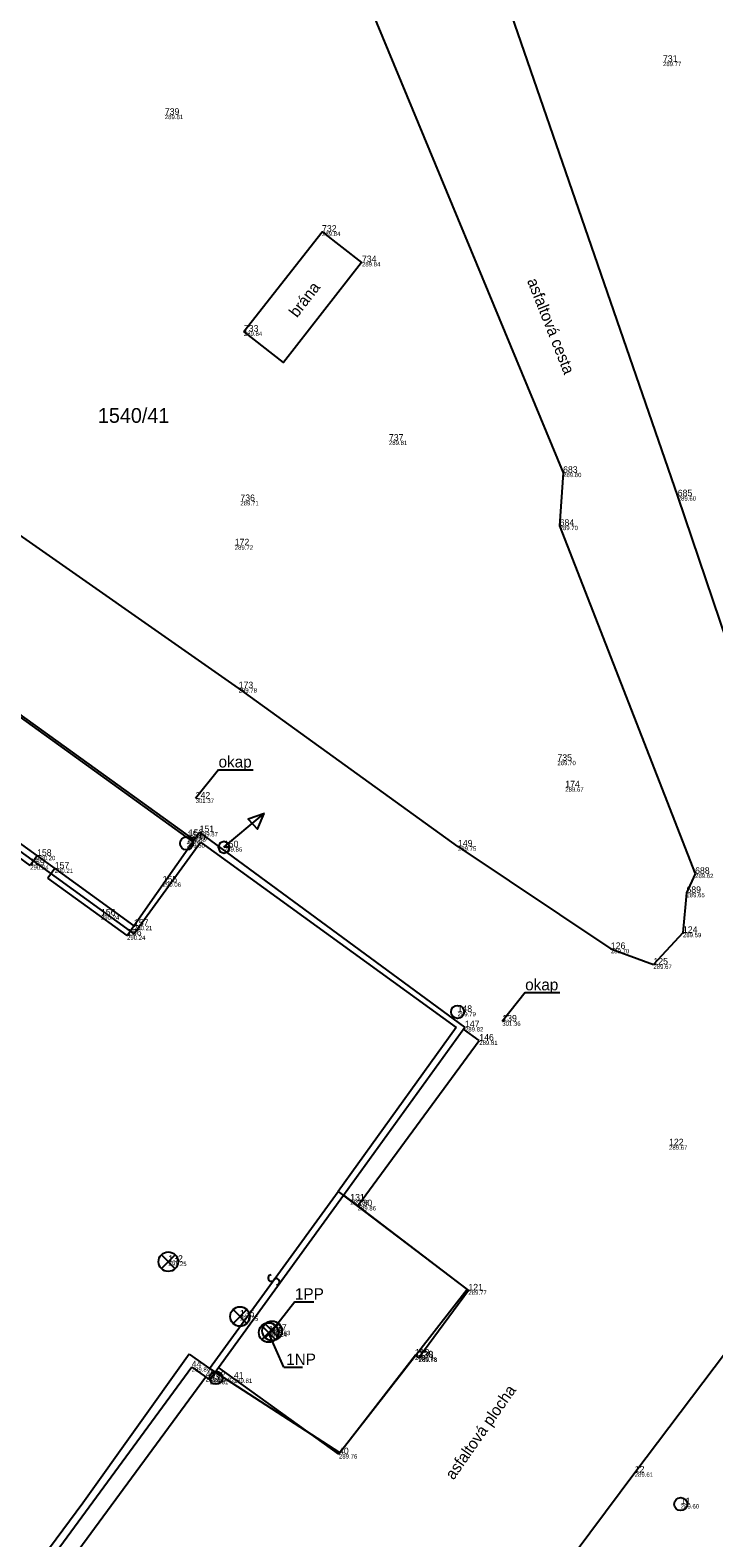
# Model space of a CAD drawing. Extents: x -805057 to -804930, y -994399 to -994240.
# Drawn here: x -804995.35 to -804979.61, y -994342.6 to -994307.89 of the extents above; entities that cross this region are included whole.
import ezdxf

# ---------------------------------------------------------------- set-up
doc = ezdxf.new("R2010")
doc.units = 0
for name, color, linetype in [('bod cislo', 7, 'Continuous'), ('bod pozice', 7, 'Continuous'), ('bod výška', 7, 'Continuous'), ('branka', 7, 'Continuous'), ('budova', 7, 'Continuous'), ('kanalizace', 7, 'Continuous'), ('Katastralni mapa', 7, 'Continuous'), ('komunikace', 7, 'Continuous'), ('podlaha', 7, 'Continuous'), ('popis', 7, 'Continuous'), ('svod', 7, 'Continuous'), ('zemnění', 7, 'Continuous')]:
    doc.layers.add(name, color=color, linetype=linetype)

msp = doc.modelspace()

# ---------------------------------------------------------------- linework, layer by layer
at = {"layer": 'bod pozice'}
for p, q in [((-804980.78, -994308.62), (-804980.78, -994308.62)), ((-804992.25, -994309.84), (-804992.25, -994309.84)), ((-804988.63, -994312.53), (-804988.63, -994312.53)), ((-804987.71, -994313.23), (-804987.71, -994313.23)), ((-804990.43, -994314.83), (-804990.43, -994314.83)), ((-804987.09, -994317.34), (-804987.09, -994317.34)), ((-804983.08, -994318.08), (-804983.08, -994318.08)), ((-804990.51, -994318.73), (-804990.51, -994318.73)), ((-804980.44, -994318.62), (-804980.44, -994318.62)), ((-804983.16, -994319.3), (-804983.16, -994319.3)), ((-804990.64, -994319.75), (-804990.64, -994319.75)), ((-804990.55, -994323.04), (-804990.55, -994323.04)), ((-804983.21, -994324.71), (-804983.21, -994324.71)), ((-804983.03, -994325.32), (-804983.03, -994325.32)), ((-804991.54, -994325.58), (-804991.54, -994325.58)), ((-804991.45, -994326.35), (-804991.45, -994326.35)), ((-804991.75, -994326.61), (-804991.75, -994326.61)), ((-804991.73, -994326.48), (-804991.73, -994326.48)), ((-804991.7, -994326.44), (-804991.7, -994326.44)), ((-804990.89, -994326.7), (-804990.89, -994326.7)), ((-804985.5, -994326.68), (-804985.5, -994326.68)), ((-804995.192, -994326.897), (-804995.192, -994326.897)), ((-804995.35, -994327.115), (-804995.35, -994327.115)), ((-804994.785, -994327.191), (-804994.785, -994327.191)), ((-804980.04, -994327.31), (-804980.04, -994327.31)), ((-804992.3, -994327.51), (-804992.3, -994327.51)), ((-804980.24, -994327.75), (-804980.24, -994327.75)), ((-804993.72, -994328.27), (-804993.72, -994328.27)), ((-804993.119, -994328.731), (-804993.119, -994328.731)), ((-804992.96, -994328.509), (-804992.96, -994328.509)), ((-804980.32, -994328.67), (-804980.32, -994328.67)), ((-804981.98, -994329.04), (-804981.98, -994329.04)), ((-804981, -994329.4), (-804981, -994329.4)), ((-804985.51, -994330.49), (-804985.51, -994330.49)), ((-804985.339, -994330.84), (-804985.339, -994330.84)), ((-804984.48, -994330.71), (-804984.48, -994330.71)), ((-804985.01, -994331.15), (-804985.01, -994331.15)), ((-804980.64, -994333.56), (-804980.64, -994333.56)), ((-804987.98, -994334.83), (-804987.98, -994334.83)), ((-804987.81, -994334.96), (-804987.81, -994334.96)), ((-804992.17, -994336.24), (-804992.17, -994336.24)), ((-804985.26, -994336.9), (-804985.26, -994336.9)), ((-804990.52, -994337.5), (-804990.52, -994337.5)), ((-804989.86, -994337.87), (-804989.86, -994337.87)), ((-804989.78, -994337.83), (-804989.78, -994337.83)), ((-804986.49, -994338.4), (-804986.49, -994338.4)), ((-804986.41, -994338.44), (-804986.41, -994338.44)), ((-804986.4, -994338.45), (-804986.4, -994338.45)), ((-804991.63, -994338.67), (-804991.63, -994338.67)), ((-804991.31, -994338.9), (-804991.31, -994338.9)), ((-804991.07, -994338.91), (-804991.07, -994338.91)), ((-804991.21, -994338.96), (-804991.21, -994338.96)), ((-804990.66, -994338.93), (-804990.66, -994338.93)), ((-804988.24, -994340.67), (-804988.24, -994340.67)), ((-804981.43, -994341.09), (-804981.43, -994341.09)), ((-804980.37, -994341.82), (-804980.37, -994341.82))]:
    msp.add_line(p, q, dxfattribs=at)
at = {"layer": 'branka'}
msp.add_lwpolyline([(-804990.43, -994314.83), (-804988.63, -994312.53), (-804987.72, -994313.242), (-804989.52, -994315.542)], close=True, dxfattribs=at)
at = {"layer": 'budova'}
for p, q in [((-804995.351, -994327.116), (-804997.375, -994325.652)), ((-804997.217, -994325.433), (-804995.192, -994326.897)), ((-804992.96, -994328.509), (-804991.45, -994326.35)), ((-804985.339, -994330.84), (-804991.45, -994326.35)), ((-804995.192, -994326.897), (-804995.351, -994327.116)), ((-804995.192, -994326.897), (-804994.785, -994327.191)), ((-804994.785, -994327.191), (-804994.944, -994327.411)), ((-804993.119, -994328.731), (-804994.944, -994327.411)), ((-804994.785, -994327.191), (-804992.96, -994328.509)), ((-804993.119, -994328.731), (-804992.96, -994328.509)), ((-804988.139, -994334.709), (-804985.339, -994330.84)), ((-804991.014, -994338.676), (-804988.139, -994334.709)), ((-804988.139, -994334.709), (-804985.26, -994336.9)), ((-804985.26, -994336.9), (-804986.4, -994338.45)), ((-804986.48, -994338.391), (-804988.24, -994340.67)), ((-804986.4, -994338.45), (-804986.48, -994338.391)), ((-804991.63, -994338.67), (-804995.51, -994343.96)), ((-804991.63, -994338.67), (-804991.21, -994338.96)), ((-804991.21, -994338.96), (-804991.014, -994338.676)), ((-804988.24, -994340.67), (-804991.014, -994338.676))]:
    msp.add_line(p, q, dxfattribs=at)
at = {"layer": 'kanalizace'}
msp.add_circle((-804980.37, -994341.82), 0.15, dxfattribs=at)
at = {"layer": 'Katastralni mapa'}
for points in [[(-805016.69, -994311.49), (-804992.96, -994328.69)], [(-804992.96, -994328.69), (-804991.43, -994326.58)], [(-804991.43, -994326.58), (-804985.54, -994330.85)], [(-804985.54, -994330.85), (-804988.26, -994334.62)], [(-804991.22, -994338.7), (-804988.26, -994334.62)], [(-804988.26, -994334.62), (-804985.29, -994336.88)], [(-804985.29, -994336.88), (-804988.22, -994340.64)], [(-804991.69, -994338.37), (-804994.14, -994341.8)], [(-804991.69, -994338.37), (-804991.22, -994338.7)], [(-804988.22, -994340.64), (-804991.22, -994338.7)], [(-804994.14, -994341.8), (-804995.54, -994343.69)]]:
    msp.add_lwpolyline(points, dxfattribs=at)
for centre, radius, start, end in [((-804989.799, -994336.616), 0.0737, 92.7957, 323.2884), ((-804989.681, -994336.703), 0.0736, 272.3237, 145.1495)]:
    msp.add_arc(centre, radius, start, end, dxfattribs=at)
at = {"layer": 'komunikace'}
for p, q in [((-804980.44, -994318.62), (-804984.8, -994305.98)), ((-804987.79, -994306.71), (-804983.08, -994318.08)), ((-804983.08, -994318.08), (-804983.16, -994319.3)), ((-804990.55, -994323.04), (-804997.35, -994318.28)), ((-804978.01, -994325.8), (-804980.44, -994318.62)), ((-804983.16, -994319.3), (-804980.04, -994327.31)), ((-804991.576, -994326.53), (-804999.45, -994320.86)), ((-804999.47, -994320.9), (-804991.604, -994326.571)), ((-804985.5, -994326.68), (-804990.55, -994323.04)), ((-804985.5, -994326.68), (-804981.98, -994329.04)), ((-804980.04, -994327.31), (-804980.24, -994327.75)), ((-804980.24, -994327.75), (-804980.32, -994328.67)), ((-804980.32, -994328.67), (-804981, -994329.4)), ((-804981.98, -994329.04), (-804981, -994329.4)), ((-804985.01, -994331.15), (-804985.373, -994330.887)), ((-804987.81, -994334.96), (-804985.01, -994331.15)), ((-804981.43, -994341.09), (-804977.38, -994335.73)), ((-804995.46, -994344.53), (-804991.31, -994338.9)), ((-804986.49, -994347.88), (-804981.43, -994341.09))]:
    msp.add_line(p, q, dxfattribs=at)
at = {"layer": 'podlaha'}
for p, q in [((-804992.329, -994336.398), (-804992.012, -994336.082)), ((-804992.012, -994336.401), (-804992.329, -994336.082)), ((-804990.679, -994337.658), (-804990.362, -994337.342)), ((-804990.362, -994337.661), (-804990.679, -994337.342)), ((-804990.019, -994338.028), (-804989.702, -994337.712)), ((-804989.702, -994338.031), (-804990.019, -994337.712)), ((-804989.939, -994337.988), (-804989.622, -994337.672)), ((-804989.622, -994337.991), (-804989.939, -994337.672))]:
    msp.add_line(p, q, dxfattribs=at)
for centre in [(-804992.17, -994336.24), (-804990.52, -994337.5), (-804989.86, -994337.87), (-804989.78, -994337.83)]:
    msp.add_circle(centre, 0.225, dxfattribs=at)
at = {"layer": 'popis'}
for p, q in [((-804991.013, -994324.916), (-804991.54, -994325.58)), ((-804991.013, -994324.916), (-804990.214, -994324.916)), ((-804983.953, -994330.046), (-804984.48, -994330.71)), ((-804983.953, -994330.046), (-804983.154, -994330.046)), ((-804989.253, -994337.166), (-804989.78, -994337.83)), ((-804989.253, -994337.166), (-804988.822, -994337.166)), ((-804989.513, -994338.668), (-804989.86, -994337.87)), ((-804989.513, -994338.668), (-804989.082, -994338.668))]:
    msp.add_line(p, q, dxfattribs=at)
at = {"layer": 'svod'}
for centre in [(-804991.75, -994326.61), (-804985.51, -994330.49), (-804991.07, -994338.91)]:
    msp.add_circle(centre, 0.15, dxfattribs=at)
at = {"layer": 'zemnění'}
msp.add_line((-804990.89, -994326.7), (-804990.006, -994325.959), dxfattribs=at)
msp.add_lwpolyline([(-804989.954, -994325.92), (-804990.334, -994326.056), (-804990.118, -994326.284), (-804989.966, -994325.921)], close=True, dxfattribs=at)
msp.add_lwpolyline([(-804990.756, -994326.7), (-804990.795, -994326.605), (-804990.89, -994326.566), (-804990.985, -994326.605), (-804991.024, -994326.7), (-804990.985, -994326.795), (-804990.89, -994326.834), (-804990.795, -994326.795), (-804990.756, -994326.7), (-804990.89, -994326.7)], dxfattribs=at)

# ---------------------------------------------------------------- texts
at = {"layer": 'bod cislo'}
for s, p in [('731    ', (-804980.78, -994308.62)), ('739    ', (-804992.25, -994309.84)), ('732    ', (-804988.63, -994312.53)), ('734    ', (-804987.71, -994313.23)), ('733    ', (-804990.43, -994314.83)), ('737    ', (-804987.09, -994317.34)), ('683    ', (-804983.08, -994318.08)), ('736    ', (-804990.51, -994318.73)), ('685    ', (-804980.44, -994318.62)), ('684    ', (-804983.16, -994319.3)), ('172    ', (-804990.64, -994319.75)), ('173    ', (-804990.55, -994323.04)), ('735    ', (-804983.21, -994324.71)), ('174    ', (-804983.03, -994325.32)), ('242    ', (-804991.54, -994325.58)), ('154    ', (-804991.73, -994326.48)), ('153    ', (-804991.7, -994326.44)), ('151    ', (-804991.45, -994326.35)), ('158    ', (-804995.192, -994326.897)), ('152    ', (-804991.75, -994326.61)), ('150    ', (-804990.89, -994326.7)), ('149    ', (-804985.5, -994326.68)), ('159    ', (-804995.35, -994327.115)), ('157    ', (-804994.785, -994327.191)), ('155    ', (-804992.3, -994327.51)), ('688    ', (-804980.04, -994327.31)), ('689    ', (-804980.24, -994327.75)), ('156    ', (-804993.72, -994328.27)), ('157    ', (-804992.96, -994328.509)), ('156    ', (-804993.119, -994328.731)), ('124    ', (-804980.32, -994328.67)), ('126    ', (-804981.98, -994329.04)), ('125    ', (-804981, -994329.4)), ('148    ', (-804985.51, -994330.49)), ('139    ', (-804984.48, -994330.71)), ('147    ', (-804985.339, -994330.84)), ('146    ', (-804985.01, -994331.15)), ('122    ', (-804980.64, -994333.56)), ('131    ', (-804987.98, -994334.83)), ('130    ', (-804987.81, -994334.96)), ('132    ', (-804992.17, -994336.24)), ('121    ', (-804985.26, -994336.9)), ('135    ', (-804990.52, -994337.5)), ('136    ', (-804989.86, -994337.87)), ('137    ', (-804989.78, -994337.83)), ('44    ', (-804991.63, -994338.67)), ('119    ', (-804986.49, -994338.4)), ('120    ', (-804986.41, -994338.44)), ('138    ', (-804986.4, -994338.45)), ('45    ', (-804991.31, -994338.9)), ('43    ', (-804991.21, -994338.96)), ('42    ', (-804991.07, -994338.91)), ('41    ', (-804990.66, -994338.93)), ('40    ', (-804988.24, -994340.67)), ('12    ', (-804981.43, -994341.09)), ('11    ', (-804980.37, -994341.82))]:
    msp.add_text(s, height=0.15, dxfattribs=at).set_placement(p)
at = {"layer": 'bod výška'}
for s, p in [('289.77  ', (-804980.78, -994308.72)), ('289.81  ', (-804992.25, -994309.94)), ('289.84  ', (-804988.63, -994312.63)), ('289.84  ', (-804987.71, -994313.33)), ('289.84  ', (-804990.43, -994314.93)), ('289.81  ', (-804987.09, -994317.44)), ('289.80  ', (-804983.08, -994318.18)), ('289.71  ', (-804990.51, -994318.83)), ('289.60  ', (-804980.44, -994318.72)), ('289.70  ', (-804983.16, -994319.4)), ('289.72  ', (-804990.64, -994319.85)), ('289.78  ', (-804990.55, -994323.14)), ('289.70  ', (-804983.21, -994324.81)), ('289.67  ', (-804983.03, -994325.42)), ('301.37  ', (-804991.54, -994325.68)), ('289.87  ', (-804991.45, -994326.45)), ('289.80  ', (-804991.75, -994326.71)), ('289.88  ', (-804991.73, -994326.58)), ('289.86  ', (-804991.7, -994326.54)), ('289.86  ', (-804990.89, -994326.8)), ('289.75  ', (-804985.5, -994326.78)), ('290.20  ', (-804995.192, -994326.997)), ('290.24  ', (-804995.35, -994327.215)), ('290.21  ', (-804994.785, -994327.291)), ('289.62  ', (-804980.04, -994327.41)), ('290.06  ', (-804992.3, -994327.61)), ('289.65  ', (-804980.24, -994327.85)), ('290.24  ', (-804993.72, -994328.37)), ('290.24  ', (-804993.119, -994328.831)), ('290.21  ', (-804992.96, -994328.609)), ('289.59  ', (-804980.32, -994328.77)), ('289.70  ', (-804981.98, -994329.14)), ('289.67  ', (-804981, -994329.5)), ('289.79  ', (-804985.51, -994330.59)), ('289.82  ', (-804985.339, -994330.94)), ('301.36  ', (-804984.48, -994330.81)), ('289.81  ', (-804985.01, -994331.25)), ('289.67  ', (-804980.64, -994333.66)), ('289.88  ', (-804987.98, -994334.93)), ('289.86  ', (-804987.81, -994335.06)), ('291.25  ', (-804992.17, -994336.34)), ('289.77  ', (-804985.26, -994337)), ('291.25  ', (-804990.52, -994337.6)), ('291.24  ', (-804989.86, -994337.97)), ('288.63  ', (-804989.78, -994337.93)), ('289.77  ', (-804986.49, -994338.5)), ('289.78  ', (-804986.41, -994338.54)), ('289.78  ', (-804986.4, -994338.55)), ('289.84  ', (-804991.63, -994338.77)), ('289.82  ', (-804991.31, -994339)), ('289.82  ', (-804991.07, -994339.01)), ('289.81  ', (-804991.21, -994339.06)), ('289.81  ', (-804990.66, -994339.03)), ('289.76  ', (-804988.24, -994340.77)), ('289.61  ', (-804981.43, -994341.19)), ('289.60  ', (-804980.37, -994341.92))]:
    msp.add_text(s, height=0.1, dxfattribs=at).set_placement(p)
at = {"layer": 'Katastralni mapa'}
msp.add_text('1540/41', height=0.34, dxfattribs=at).set_placement((-804993.79, -994316.93))
at = {"layer": 'popis'}
for s, height, rotation, p in [('brána', 0.2629, 52.5685, (-804989.205, -994314.526)), ('asfaltová cesta', 0.26289, 291.5936, (-804983.914, -994313.658)), ('asfaltová plocha', 0.26289, 55.131, (-804985.601, -994341.278))]:
    msp.add_text(s, height=height, rotation=rotation, dxfattribs=at).set_placement(p)
for s, p in [('okap', (-804991.013, -994324.863)), ('okap', (-804983.953, -994329.993)), ('1PP', (-804989.253, -994337.113)), ('1NP', (-804989.455, -994338.616))]:
    msp.add_text(s, height=0.2629, dxfattribs=at).set_placement(p)

doc.saveas('drawing.dxf')
